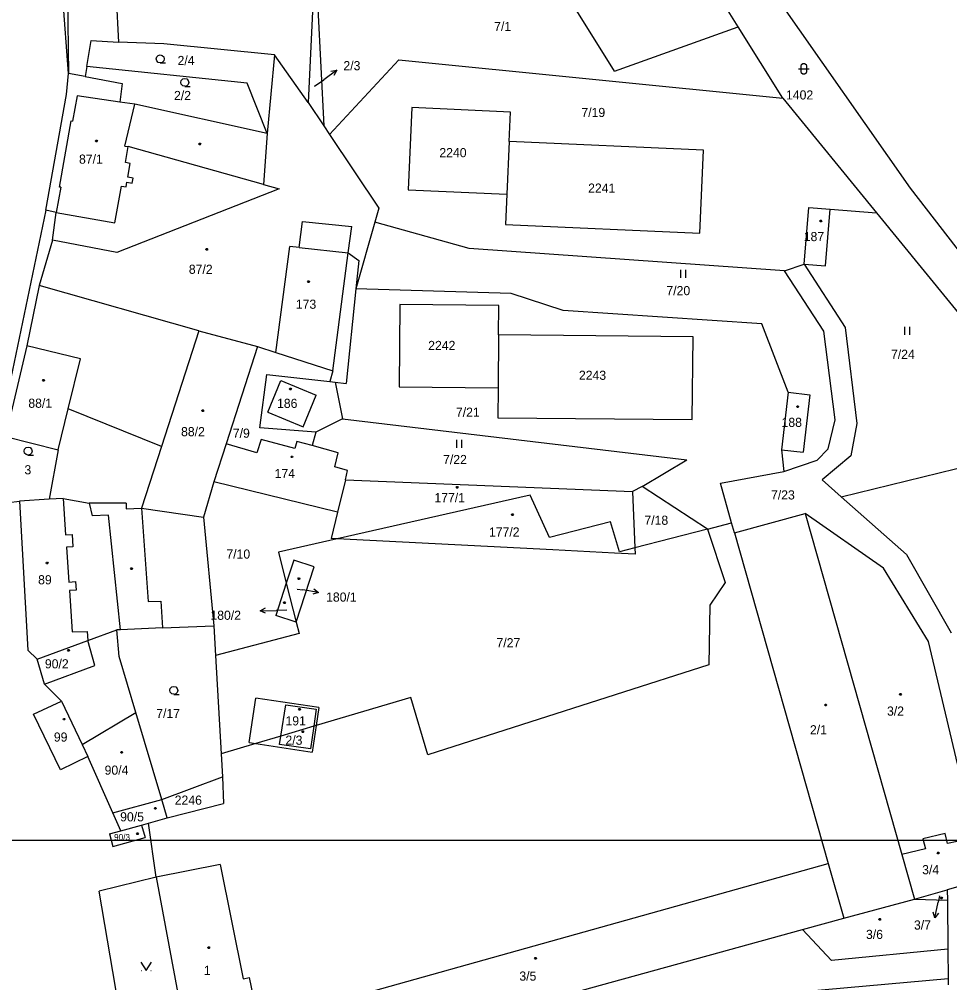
# Model space of a CAD drawing. Extents: x -802857 to -799647, y -1020285 to -1015884.
# Drawn here: x -801490 to -801316.9, y -1017640.2 to -1017461.1 of the extents above; entities that cross this region are included whole.
import ezdxf

# ---------------------------------------------------------------- set-up
doc = ezdxf.new("R2010")
doc.units = 0
for name, color, linetype in [('Default', 7, 'Continuous'), ('KN_HRANICE', 7, 'Continuous'), ('KN_KULTURY', 7, 'Continuous'), ('KN_PARCELY', 7, 'Continuous'), ('KN_SLUCKY', 7, 'Continuous'), ('LEGENDA', 7, 'Continuous')]:
    doc.layers.add(name, color=color, linetype=linetype)

# ---------------------------------------------------------------- blocks, each defined once
blk = doc.blocks.new('304')
at = {"layer": 'Default'}
blk.add_lwpolyline([(0, 0), (-0.38, 0.1), (-0.65, 0.37), (-0.75, 0.74), (-0.65, 1.11), (-0.38, 1.38), (-0.01, 1.48), (0.36, 1.38), (0.63, 1.11), (0.73, 0.73), (0.63, 0.35), (0.36, 0.08), (-0.02, -0.02), (0.98, -0.02)], dxfattribs=at)
blk = doc.blocks.new('306')
at = {"layer": 'Default'}
for p, q in [((-0.5, 1.5), (-0.5, 0)), ((0.5, 0), (0.5, 1.5))]:
    blk.add_line(p, q, dxfattribs=at)
blk = doc.blocks.new('314')
at = {"layer": 'Default'}
for p, q in [((-0.95, 0), (-0.85, 0)), ((0.85, 0), (0.95, 0))]:
    blk.add_line(p, q, dxfattribs=at)
blk.add_lwpolyline([(-1, 1.5), (0, 0), (1, 1.5)], dxfattribs=at)
blk = doc.blocks.new('316')
at = {"layer": 'Default'}
for points in [[(-0.5, 1.5), (-0.4, 1.79), (-0.15, 1.97), (0.16, 1.97), (0.41, 1.79), (0.51, 1.5), (0.51, 0.5), (0.41, 0.21), (0.16, 0.03), (-0.15, 0.03), (-0.4, 0.21), (-0.5, 0.5), (-0.5, 1.5)], [(-1, 1), (0.27, 1), (1, 1)]]:
    blk.add_lwpolyline(points, dxfattribs=at)
blk = doc.blocks.new('NAHRADNI_SYMBOL')
at = {"layer": 'Default'}
blk.add_lwpolyline([(0.09, 0.15), (0.18, 0), (0.09, -0.15), (-0.09, -0.15), (-0.18, 0), (-0.09, 0.15), (0.09, 0.15)], dxfattribs=at)
blk = doc.blocks.new('10292')
at = {"layer": 'Default'}
blk.add_line((0, 3), (0, 0), dxfattribs=at)
blk.add_lwpolyline([(-0.5, 2), (0, 3), (0.5, 2)], dxfattribs=at)
blk = doc.blocks.new('402')
at = {"layer": 'Default'}
blk.add_lwpolyline([(0.09, 0.15), (0.18, 0), (0.09, -0.15), (-0.09, -0.15), (-0.18, 0), (-0.09, 0.15), (0.09, 0.15)], dxfattribs=at)

msp = doc.modelspace()

# ---------------------------------------------------------------- linework, layer by layer
at = {"layer": 'KN_HRANICE'}
for p, q in [((-801366.39, -1017432.38), (-801324.28, -1017492.5)), ((-801356.25, -1017462.47), (-801367.72, -1017444.15)), ((-801435.08, -1017451.54), (-801436.26, -1017476.56)), ((-801481.05, -1017452.5), (-801480.85, -1017471.15)), ((-801472.2, -1017452.64), (-801471.55, -1017465.31)), ((-801379.24, -1017470.71), (-801390.25, -1017453.11)), ((-801480.85, -1017471.15), (-801481.99, -1017455.66)), ((-801434.42, -1017459.09), (-801433.35, -1017480.9)), ((-801379.24, -1017470.71), (-801356.25, -1017462.47)), ((-801347.93, -1017475.78), (-801356.25, -1017462.47)), ((-801477.42, -1017469.86), (-801476.6, -1017465.01)), ((-801476.6, -1017465.01), (-801471.55, -1017465.31)), ((-801463.11, -1017465.64), (-801471.55, -1017465.31)), ((-801442.53, -1017467.71), (-801463.11, -1017465.64)), ((-801442.53, -1017467.71), (-801443.87, -1017482.3)), ((-801436.26, -1017476.56), (-801442.53, -1017467.71)), ((-801432.29, -1017482.48), (-801419.41, -1017468.61)), ((-801419.41, -1017468.61), (-801347.93, -1017475.78)), ((-801481.2, -1017475.07), (-801480.85, -1017471.15)), ((-801477.74, -1017471.72), (-801480.85, -1017471.15)), ((-801477.42, -1017469.86), (-801477.74, -1017471.72)), ((-801447.58, -1017472.97), (-801477.42, -1017469.86)), ((-801477.74, -1017471.72), (-801470.85, -1017473.01)), ((-801470.85, -1017473.01), (-801471.25, -1017476.47)), ((-801443.87, -1017482.3), (-801447.58, -1017472.97)), ((-801485.05, -1017496.6), (-801481.2, -1017475.07)), ((-801468.51, -1017476.86), (-801471.25, -1017476.47)), ((-801436.26, -1017476.56), (-801433.35, -1017480.9)), ((-801347.93, -1017475.78), (-801330.52, -1017497.1)), ((-801443.87, -1017482.3), (-801468.51, -1017476.86)), ((-801416.99, -1017477.52), (-801417.67, -1017492.81)), ((-801398.61, -1017478.34), (-801416.99, -1017477.52)), ((-801398.85, -1017483.83), (-801398.61, -1017478.34)), ((-801433.35, -1017480.9), (-801432.29, -1017482.48)), ((-801443.87, -1017482.3), (-801444.57, -1017491.8)), ((-801432.29, -1017482.48), (-801423.09, -1017496.22)), ((-801398.85, -1017483.83), (-801399.29, -1017493.63)), ((-801362.69, -1017485.45), (-801398.85, -1017483.83)), ((-801363.38, -1017500.83), (-801362.69, -1017485.45)), ((-801441.67, -1017492.59), (-801471.82, -1017504.46)), ((-801444.57, -1017491.8), (-801441.67, -1017492.59)), ((-801324.28, -1017492.5), (-801277.94, -1017552.4)), ((-801417.67, -1017492.81), (-801399.29, -1017493.63)), ((-801399.29, -1017493.63), (-801399.54, -1017499.22)), ((-801423.09, -1017496.22), (-801423.84, -1017498.84)), ((-801343.98, -1017506.62), (-801343.11, -1017496.06)), ((-801343.11, -1017496.06), (-801339.17, -1017496.38)), ((-801485.05, -1017496.6), (-801499.12, -1017563.93)), ((-801483.09, -1017497), (-801485.05, -1017496.6)), ((-801483.78, -1017502.18), (-801483.09, -1017497)), ((-801340.04, -1017506.94), (-801339.17, -1017496.38)), ((-801339.17, -1017496.38), (-801330.52, -1017497.1)), ((-801330.52, -1017497.1), (-801295.7, -1017539.76)), ((-801437.92, -1017503.51), (-801437.29, -1017498.66)), ((-801437.29, -1017498.66), (-801428.14, -1017499.64)), ((-801428.78, -1017504.49), (-801428.14, -1017499.64)), ((-801423.84, -1017498.84), (-801427.36, -1017511.23)), ((-801406.29, -1017503.73), (-801423.84, -1017498.84)), ((-801399.54, -1017499.22), (-801363.38, -1017500.83)), ((-801483.78, -1017502.18), (-801486.27, -1017510.58)), ((-801471.82, -1017504.46), (-801483.78, -1017502.18)), ((-801442.26, -1017523.04), (-801439.66, -1017503.32)), ((-801437.92, -1017503.51), (-801439.66, -1017503.32)), ((-801428.78, -1017504.49), (-801426.82, -1017505.92)), ((-801347.66, -1017507.88), (-801406.29, -1017503.73)), ((-801426.82, -1017505.92), (-801427.36, -1017511.23)), ((-801347.66, -1017507.88), (-801343.98, -1017506.62)), ((-801343.98, -1017506.62), (-801336.36, -1017518.38)), ((-801343.98, -1017506.62), (-801340.04, -1017506.94)), ((-801340.3, -1017519.09), (-801347.66, -1017507.88)), ((-801486.27, -1017510.58), (-801488.6, -1017521.78)), ((-801456.61, -1017519.04), (-801486.27, -1017510.58)), ((-801427.36, -1017511.23), (-801429.15, -1017528.81)), ((-801398.49, -1017512.08), (-801427.36, -1017511.23)), ((-801388.8, -1017515.22), (-801398.49, -1017512.08)), ((-801419.19, -1017514.13), (-801419.33, -1017529.43)), ((-801400.8, -1017514.3), (-801419.19, -1017514.13)), ((-801400.84, -1017519.79), (-801400.8, -1017514.3)), ((-801351.85, -1017517.73), (-801388.8, -1017515.22)), ((-801346.97, -1017530.44), (-801351.85, -1017517.73)), ((-801456.61, -1017519.04), (-801445.68, -1017521.95)), ((-801338.24, -1017535.6), (-801340.3, -1017519.09)), ((-801336.36, -1017518.38), (-801334.2, -1017536.23)), ((-801400.84, -1017519.79), (-801400.93, -1017529.6)), ((-801364.65, -1017520.13), (-801400.84, -1017519.79)), ((-801364.79, -1017535.52), (-801364.65, -1017520.13)), ((-801488.6, -1017521.78), (-801492.54, -1017538.69)), ((-801478.58, -1017524.23), (-801488.6, -1017521.78)), ((-801445.68, -1017521.95), (-801451.5, -1017540.03)), ((-801445.68, -1017521.95), (-801442.26, -1017523.04)), ((-801442.26, -1017523.04), (-801431.67, -1017526.43)), ((-801480.88, -1017533.53), (-801478.58, -1017524.23)), ((-801431.67, -1017526.43), (-801432.23, -1017528.46)), ((-801445.24, -1017537.05), (-801443.91, -1017527.13)), ((-801443.91, -1017527.13), (-801432.23, -1017528.46)), ((-801432.23, -1017528.46), (-801431.24, -1017528.57)), ((-801431.24, -1017528.57), (-801429.87, -1017535.4)), ((-801431.24, -1017528.57), (-801429.15, -1017528.81)), ((-801419.33, -1017529.43), (-801400.93, -1017529.6)), ((-801400.93, -1017529.6), (-801400.98, -1017535.2)), ((-801346.97, -1017530.44), (-801348.19, -1017541.12)), ((-801346.97, -1017530.44), (-801342.95, -1017530.9)), ((-801342.95, -1017530.9), (-801344.17, -1017541.58)), ((-801463.52, -1017540.51), (-801480.88, -1017533.53)), ((-801429.87, -1017535.4), (-801434.82, -1017537.87)), ((-801429.87, -1017535.4), (-801365.81, -1017542.99)), ((-801400.98, -1017535.2), (-801364.79, -1017535.52)), ((-801339.5, -1017540.98), (-801338.24, -1017535.6)), ((-801434.82, -1017537.87), (-801445.24, -1017537.05)), ((-801334.2, -1017536.23), (-801335.28, -1017542.24)), ((-801492.54, -1017538.69), (-801482.76, -1017541.15)), ((-801444.98, -1017539.21), (-801445.8, -1017541.72)), ((-801438.72, -1017540.9), (-801444.98, -1017539.21)), ((-801434.82, -1017537.87), (-801435.51, -1017540.35)), ((-801482.76, -1017541.15), (-801484.41, -1017550.34)), ((-801463.52, -1017540.51), (-801467.22, -1017552.01)), ((-801451.5, -1017540.03), (-801453.78, -1017547.11)), ((-801445.8, -1017541.72), (-801451.5, -1017540.03)), ((-801438.33, -1017539.58), (-801438.72, -1017540.9)), ((-801435.51, -1017540.35), (-801438.33, -1017539.58)), ((-801430.65, -1017541.69), (-801435.51, -1017540.35)), ((-801348.19, -1017541.12), (-801344.17, -1017541.58)), ((-801348.19, -1017541.12), (-801347.75, -1017545.2)), ((-801341.56, -1017543.05), (-801339.5, -1017540.98)), ((-801337.12, -1017549.87), (-801295.7, -1017539.76)), ((-801431.26, -1017544.3), (-801430.65, -1017541.69)), ((-801335.28, -1017542.24), (-801340.66, -1017546.73)), ((-801428.9, -1017544.97), (-801431.26, -1017544.3)), ((-801374.14, -1017547.98), (-801365.81, -1017542.99)), ((-801347.75, -1017545.2), (-801341.56, -1017543.05)), ((-801429.31, -1017546.73), (-801428.9, -1017544.97)), ((-801359.52, -1017547.37), (-801347.75, -1017545.2)), ((-801453.78, -1017547.11), (-801455.73, -1017553.67)), ((-801430.77, -1017552.77), (-801453.78, -1017547.11)), ((-801429.31, -1017546.73), (-801430.77, -1017552.77)), ((-801429.31, -1017546.73), (-801375.91, -1017548.92)), ((-801374.14, -1017547.98), (-801375.91, -1017548.92)), ((-801361.94, -1017555.93), (-801374.14, -1017547.98)), ((-801357.47, -1017554.71), (-801359.52, -1017547.37)), ((-801340.66, -1017546.73), (-801337.12, -1017549.87)), ((-801394.95, -1017549.57), (-801430.88, -1017557.72)), ((-801391.34, -1017557.45), (-801394.95, -1017549.57)), ((-801375.91, -1017548.92), (-801375.48, -1017559.38)), ((-801337.12, -1017549.87), (-801324.97, -1017560.63)), ((-801495.13, -1017551.32), (-801489.95, -1017550.72)), ((-801484.41, -1017550.34), (-801489.95, -1017550.72)), ((-801489.95, -1017550.72), (-801488.39, -1017578.43)), ((-801481.83, -1017550.17), (-801484.41, -1017550.34)), ((-801481.83, -1017550.17), (-801476.99, -1017551.09)), ((-801470.08, -1017551.09), (-801476.99, -1017551.09)), ((-801470.08, -1017551.09), (-801470.08, -1017552.09)), ((-801470.08, -1017552.09), (-801467.22, -1017552.01)), ((-801467.22, -1017552.01), (-801455.73, -1017553.67)), ((-801455.73, -1017553.67), (-801453.77, -1017573.85)), ((-801430.77, -1017552.77), (-801431.96, -1017557.66)), ((-801356.95, -1017556.58), (-801343.82, -1017553)), ((-801329.23, -1017563.15), (-801343.82, -1017553)), ((-801343.82, -1017553), (-801325.84, -1017616.37)), ((-801380, -1017554.55), (-801391.34, -1017557.45)), ((-801378.36, -1017560.12), (-801380, -1017554.55)), ((-801361.94, -1017555.93), (-801357.47, -1017554.71)), ((-801356.95, -1017556.58), (-801357.47, -1017554.71)), ((-801361.94, -1017555.93), (-801375.48, -1017559.38)), ((-801361.94, -1017555.93), (-801358.7, -1017565.82)), ((-801430.88, -1017557.72), (-801441.78, -1017560.19)), ((-801430.88, -1017557.72), (-801431.96, -1017557.66)), ((-801390.75, -1017559.77), (-801430.88, -1017557.72)), ((-801441.78, -1017560.19), (-801440.32, -1017565.92)), ((-801379.28, -1017560.36), (-801390.75, -1017559.77)), ((-801375.43, -1017560.56), (-801379.28, -1017560.36)), ((-801375.48, -1017559.38), (-801378.36, -1017560.12)), ((-801375.48, -1017559.38), (-801375.43, -1017560.56)), ((-801324.97, -1017560.63), (-801316.63, -1017575.17)), ((-801438.93, -1017561.69), (-801440.32, -1017565.92)), ((-801435.13, -1017562.93), (-801438.93, -1017561.69)), ((-801438.46, -1017573.2), (-801435.13, -1017562.93)), ((-801320.87, -1017576.78), (-801329.23, -1017563.15)), ((-801440.32, -1017565.92), (-801442.26, -1017571.97)), ((-801440.32, -1017565.92), (-801438.46, -1017573.2)), ((-801358.7, -1017565.82), (-801361.51, -1017570.05)), ((-801361.51, -1017570.05), (-801361.71, -1017581.12)), ((-801438.46, -1017573.2), (-801442.26, -1017571.97)), ((-801438.46, -1017573.2), (-801437.91, -1017575.33)), ((-801477.2, -1017576.6), (-801471.83, -1017574.62)), ((-801471.14, -1017574.59), (-801471.83, -1017574.62)), ((-801471.38, -1017579.57), (-801471.83, -1017574.62)), ((-801463.35, -1017574.26), (-801471.14, -1017574.59)), ((-801463.35, -1017574.26), (-801453.77, -1017573.85)), ((-801453.77, -1017573.85), (-801453.46, -1017579.4)), ((-801486.65, -1017580.08), (-801477.2, -1017576.6)), ((-801437.91, -1017575.33), (-801453.46, -1017579.4)), ((-801314.53, -1017603.45), (-801320.87, -1017576.78)), ((-801486.65, -1017580.08), (-801488.39, -1017578.43)), ((-801485.28, -1017584.71), (-801486.65, -1017580.08)), ((-801468.32, -1017590), (-801471.38, -1017579.57)), ((-801453.46, -1017579.4), (-801452.43, -1017597.66)), ((-801361.71, -1017581.12), (-801413.99, -1017597.89)), ((-801482.14, -1017587.87), (-801485.28, -1017584.71)), ((-801447.25, -1017595.56), (-801446, -1017587.3)), ((-801434.27, -1017589.08), (-801446, -1017587.3)), ((-801417.15, -1017587.18), (-801434.77, -1017592.42)), ((-801413.99, -1017597.89), (-801417.15, -1017587.18)), ((-801487.31, -1017590.29), (-801482.14, -1017587.87)), ((-801482.14, -1017587.87), (-801478.31, -1017595.94)), ((-801434.27, -1017589.08), (-801434.77, -1017592.42)), ((-801482.34, -1017600.68), (-801487.31, -1017590.29)), ((-801478.31, -1017595.94), (-801468.32, -1017590)), ((-801463.49, -1017606.2), (-801468.32, -1017590)), ((-801435.2, -1017592.55), (-801441.33, -1017594.37)), ((-801434.77, -1017592.42), (-801435.52, -1017597.34)), ((-801434.77, -1017592.42), (-801435.2, -1017592.55)), ((-801441.33, -1017594.37), (-801446, -1017595.75)), ((-801478.31, -1017595.94), (-801477.24, -1017598.19)), ((-801446, -1017595.75), (-801452.43, -1017597.66)), ((-801447.25, -1017595.56), (-801446, -1017595.75)), ((-801446, -1017595.75), (-801435.52, -1017597.34)), ((-801477.24, -1017598.19), (-801482.34, -1017600.68)), ((-801472.58, -1017608.66), (-801477.24, -1017598.19)), ((-801452.43, -1017597.66), (-801452.19, -1017601.97)), ((-801463.49, -1017606.2), (-801452.19, -1017601.97)), ((-801452.19, -1017601.97), (-801452, -1017606.94)), ((-801472.58, -1017608.66), (-801463.49, -1017606.2)), ((-801462.47, -1017609.6), (-801463.49, -1017606.2)), ((-801462.47, -1017609.6), (-801452, -1017606.94)), ((-801471.09, -1017611.99), (-801472.58, -1017608.66)), ((-801471.09, -1017611.99), (-801467.24, -1017610.92)), ((-801467.24, -1017610.92), (-801465.96, -1017610.57)), ((-801467.24, -1017610.92), (-801466.59, -1017613.23)), ((-801465.96, -1017610.57), (-801462.47, -1017609.6)), ((-801464.55, -1017620.59), (-801465.96, -1017610.57)), ((-801473.21, -1017612.58), (-801471.09, -1017611.99)), ((-801473.21, -1017612.58), (-801472.57, -1017614.89)), ((-801317.78, -1017612.5), (-801321.88, -1017613.46)), ((-801317.34, -1017614.38), (-801317.78, -1017612.5)), ((-801472.57, -1017614.89), (-801466.59, -1017613.23)), ((-801321.88, -1017613.46), (-801321.44, -1017615.34)), ((-801315.54, -1017613.96), (-801317.34, -1017614.38)), ((-801321.44, -1017615.34), (-801325.84, -1017616.37)), ((-801325.84, -1017616.37), (-801323.48, -1017624.68)), ((-801439.56, -1017646.05), (-801339.49, -1017618.1)), ((-801339.49, -1017618.1), (-801336.61, -1017628.26)), ((-801452.63, -1017618.23), (-801464.55, -1017620.59)), ((-801452.63, -1017618.23), (-801448.35, -1017639.53)), ((-801464.55, -1017620.59), (-801475.13, -1017623.23)), ((-801464.55, -1017620.59), (-801460.47, -1017642.27)), ((-801469.47, -1017656.08), (-801475.13, -1017623.23)), ((-801323.48, -1017624.68), (-801317.37, -1017622.97)), ((-801313.67, -1017621.93), (-801317.37, -1017622.97)), ((-801317.37, -1017622.97), (-801317.35, -1017624.91)), ((-801336.61, -1017628.26), (-801323.48, -1017624.68)), ((-801323.48, -1017624.68), (-801317.35, -1017624.91)), ((-801317.35, -1017624.91), (-801317.25, -1017634.01)), ((-801344.28, -1017630.37), (-801336.61, -1017628.26)), ((-801436.88, -1017655.78), (-801344.28, -1017630.37)), ((-801338.92, -1017636.13), (-801344.28, -1017630.37)), ((-801317.25, -1017634.01), (-801338.92, -1017636.13)), ((-801317.25, -1017634.01), (-801317.19, -1017639.44)), ((-801448.35, -1017639.53), (-801447.15, -1017639.26)), ((-801445.17, -1017648.98), (-801447.15, -1017639.26)), ((-801347.72, -1017642.2), (-801317.19, -1017639.44)), ((-801317.19, -1017639.44), (-801317.18, -1017640.62))]:
    msp.add_line(p, q, dxfattribs=at)
at = {"layer": 'KN_PARCELY'}
for p, q in [((-801435.04, -1017473.53), (-801433.36, -1017472.32)), ((-801438.29, -1017567.05), (-801437.26, -1017567.21)), ((-801440.24, -1017570.98), (-801442.18, -1017571.01)), ((-801318.83, -1017624.08), (-801319.08, -1017625.26))]:
    msp.add_line(p, q, dxfattribs=at)
at = {"layer": 'KN_SLUCKY'}
for p, q in [((-801479.23, -1017475.34), (-801480.06, -1017480.02)), ((-801471.25, -1017476.47), (-801479.23, -1017475.34)), ((-801470.35, -1017484.66), (-801468.51, -1017476.86)), ((-801482.5, -1017492.28), (-801480.31, -1017479.97)), ((-801480.31, -1017479.97), (-801480.06, -1017480.02)), ((-801470.35, -1017484.66), (-801469.71, -1017484.77)), ((-801470.22, -1017487.73), (-801469.71, -1017484.77)), ((-801444.57, -1017491.8), (-801469.71, -1017484.77)), ((-801469.34, -1017487.89), (-801470.22, -1017487.73)), ((-801469.78, -1017490.45), (-801469.34, -1017487.89)), ((-801468.8, -1017490.62), (-801469.78, -1017490.45)), ((-801468.96, -1017491.55), (-801468.8, -1017490.62)), ((-801482.26, -1017492.32), (-801483.09, -1017497)), ((-801482.26, -1017492.32), (-801482.5, -1017492.28)), ((-801472.18, -1017498.91), (-801470.99, -1017492.11)), ((-801470.99, -1017492.11), (-801470.1, -1017492.27)), ((-801470.1, -1017492.27), (-801469.95, -1017491.38)), ((-801469.95, -1017491.38), (-801468.96, -1017491.55)), ((-801483.09, -1017497), (-801472.18, -1017498.91)), ((-801437.92, -1017503.51), (-801428.78, -1017504.49)), ((-801431.67, -1017526.43), (-801428.78, -1017504.49)), ((-801456.61, -1017519.04), (-801463.52, -1017540.51)), ((-801443.75, -1017534.16), (-801441.3, -1017528.25)), ((-801441.3, -1017528.25), (-801434.74, -1017530.96)), ((-801437.19, -1017536.87), (-801434.74, -1017530.96)), ((-801482.76, -1017541.15), (-801480.88, -1017533.53)), ((-801443.75, -1017534.16), (-801437.19, -1017536.87)), ((-801481.83, -1017550.17), (-801481.37, -1017556.95)), ((-801476.99, -1017551.09), (-801476.44, -1017553.45)), ((-801473.4, -1017553.28), (-801476.44, -1017553.45)), ((-801471.14, -1017574.59), (-801473.4, -1017553.28)), ((-801467.22, -1017552.01), (-801466.02, -1017569.37)), ((-801481.37, -1017556.95), (-801480.17, -1017556.87)), ((-801480.17, -1017556.87), (-801480.01, -1017559.17)), ((-801356.95, -1017556.58), (-801339.49, -1017618.1)), ((-801480.01, -1017559.17), (-801481.21, -1017559.25)), ((-801481.21, -1017559.25), (-801480.77, -1017565.73)), ((-801480.77, -1017565.73), (-801479.52, -1017565.65)), ((-801479.52, -1017565.65), (-801479.41, -1017567.25)), ((-801479.41, -1017567.25), (-801480.66, -1017567.33)), ((-801480.66, -1017567.33), (-801480.14, -1017575)), ((-801466.02, -1017569.37), (-801463.67, -1017569.28)), ((-801463.67, -1017569.28), (-801463.35, -1017574.26)), ((-801480.14, -1017575), (-801477.38, -1017574.92)), ((-801477.38, -1017574.92), (-801477.2, -1017576.6)), ((-801475.91, -1017581.24), (-801477.2, -1017576.6)), ((-801485.28, -1017584.71), (-801475.91, -1017581.24)), ((-801441.33, -1017594.37), (-801440.42, -1017588.56)), ((-801440.42, -1017588.56), (-801434.75, -1017589.39)), ((-801434.75, -1017589.39), (-801435.2, -1017592.55)), ((-801435.2, -1017592.55), (-801435.81, -1017596.76)), ((-801441.57, -1017595.93), (-801441.33, -1017594.37)), ((-801435.81, -1017596.76), (-801441.57, -1017595.93))]:
    msp.add_line(p, q, dxfattribs=at)
at = {"layer": 'LEGENDA'}
msp.add_lwpolyline([(-801703.84, -1017613.71), (-800862.84, -1017613.71), (-800862.84, -1017019.71), (-801703.84, -1017019.71)], close=True, dxfattribs=at)

# ---------------------------------------------------------------- block references
at = {"layer": 'KN_KULTURY'}
for name, p in [('304', (-801463.74, -1017469.19)), ('316', (-801344.05, -1017471.3)), ('304', (-801459.19, -1017473.55)), ('402', (-801475.64, -1017483.72)), ('402', (-801456.42, -1017484.28)), ('402', (-801340.89, -1017498.58)), ('NAHRADNI_SYMBOL', (-801455.1, -1017503.86)), ('306', (-801366.49, -1017509.17)), ('402', (-801436.17, -1017509.9)), ('306', (-801324.82, -1017519.75)), ('402', (-801485.46, -1017528.24)), ('402', (-801439.54, -1017529.85)), ('402', (-801455.86, -1017533.84)), ('402', (-801345.19, -1017533.12)), ('306', (-801408.18, -1017540.8)), ('304', (-801488.34, -1017542.12)), ('402', (-801439.26, -1017542.45)), ('402', (-801408.53, -1017548.14)), ('402', (-801398.26, -1017553.22)), ('402', (-801484.8, -1017562.2)), ('402', (-801469.1, -1017563.27)), ('402', (-801437.96, -1017565.13)), ('402', (-801440.67, -1017569.55)), ('402', (-801480.82, -1017578.43)), ('304', (-801461.24, -1017586.61)), ('NAHRADNI_SYMBOL', (-801326.07, -1017586.6)), ('402', (-801437.84, -1017589.42)), ('402', (-801339.98, -1017588.59)), ('402', (-801481.65, -1017591.23)), ('402', (-801437.24, -1017593.58)), ('NAHRADNI_SYMBOL', (-801470.94, -1017597.4)), ('NAHRADNI_SYMBOL', (-801464.68, -1017607.84)), ('NAHRADNI_SYMBOL', (-801467.99, -1017612.51)), ('402', (-801319.04, -1017616.11)), ('NAHRADNI_SYMBOL', (-801318.45, -1017624.51)), ('NAHRADNI_SYMBOL', (-801329.92, -1017628.44)), ('402', (-801454.74, -1017633.73)), ('402', (-801393.95, -1017635.72)), ('314', (-801466.37, -1017637.95))]:
    msp.add_blockref(name, p, dxfattribs=at)
at = {"layer": 'KN_PARCELY'}
for p, rotation in [((-801433.36, -1017472.32), -54.155129), ((-801437.26, -1017567.21), -98.960429), ((-801442.18, -1017571.01), 90.928402), ((-801319.08, -1017625.26), 168.048521)]:
    msp.add_blockref('10292', p, dxfattribs=dict(at, rotation=rotation))

# ---------------------------------------------------------------- texts
for s, height, p in [('7/1', 1.7, (-801401.65, -1017463.26)), ('2/4', 1.7, (-801460.54, -1017469.6)), ('2/3', 1.7, (-801429.69, -1017470.56)), ('2/2', 1.7, (-801461.2, -1017476.11)), ('2/3', 0.1, (-801435.19, -1017473.53)), ('1402', 1.7, (-801347.36, -1017476)), ('7/19', 1.7, (-801385.42, -1017479.26)), ('2240', 1.7, (-801411.84, -1017486.73)), ('87/1', 1.7, (-801478.87, -1017487.94)), ('2241', 1.7, (-801384.17, -1017493.33)), ('187', 1.7, (-801344.06, -1017502.34)), ('87/2', 1.7, (-801458.44, -1017508.42)), ('7/20', 1.7, (-801369.61, -1017512.39)), ('173', 1.7, (-801438.54, -1017514.92)), ('2242', 1.7, (-801413.92, -1017522.59)), ('7/24', 1.7, (-801327.83, -1017524.23)), ('2243', 1.7, (-801385.88, -1017528.13)), ('88/1', 1.7, (-801488.3, -1017533.33)), ('186', 1.7, (-801442.04, -1017533.36)), ('7/21', 1.7, (-801408.76, -1017535)), ('188', 1.7, (-801348.19, -1017536.89)), ('88/2', 1.7, (-801459.89, -1017538.62)), ('7/9', 1.7, (-801450.26, -1017538.9)), ('7/22', 1.7, (-801411.15, -1017543.8)), ('3', 1.7, (-801489.02, -1017545.71)), ('174', 1.7, (-801442.48, -1017546.4)), ('177/1', 1.7, (-801412.76, -1017550.89)), ('7/23', 1.7, (-801350.15, -1017550.38)), ('7/18', 1.7, (-801373.7, -1017555.09)), ('177/2', 1.7, (-801402.61, -1017557.27)), ('7/10', 1.7, (-801451.46, -1017561.38)), ('89', 1.7, (-801486.48, -1017566.16)), ('180/1', 0.1, (-801438.53, -1017567.05)), ('180/1', 1.7, (-801432.91, -1017569.38)), ('180/2', 1.7, (-801454.43, -1017572.76)), ('180/2', 0.1, (-801440.49, -1017570.98)), ('7/27', 1.7, (-801401.22, -1017577.87)), ('90/2', 1.7, (-801485.22, -1017581.79)), ('7/17', 1.7, (-801464.51, -1017591.02)), ('3/2', 1.7, (-801328.57, -1017590.58)), ('191', 1.7, (-801440.47, -1017592.4)), ('2/1', 1.7, (-801342.91, -1017594.06)), ('99', 1.7, (-801483.55, -1017595.41)), ('2/3', 1.7, (-801440.47, -1017595.99)), ('90/4', 1.7, (-801474.11, -1017601.56)), ('2246', 1.7, (-801461.07, -1017607.14)), ('90/5', 1.7, (-801471.22, -1017610.24)), ('90/3', 1.14, (-801472.35, -1017613.73)), ('3/4', 1.7, (-801322.04, -1017620.08)), ('3/7', 0.1, (-801318.98, -1017624.08)), ('3/7', 1.7, (-801323.56, -1017630.36)), ('3/6', 1.7, (-801332.48, -1017632.11)), ('1', 1.7, (-801455.66, -1017638.79)), ('3/5', 1.7, (-801396.96, -1017639.86))]:
    msp.add_text(s, height=height, dxfattribs=at).set_placement(p)

doc.saveas('drawing.dxf')
